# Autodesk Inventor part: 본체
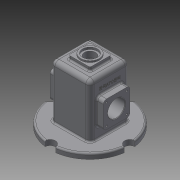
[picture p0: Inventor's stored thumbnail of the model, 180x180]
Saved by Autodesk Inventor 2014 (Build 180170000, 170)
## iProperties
Created: 2018-07
Part Number: 본체
Material: 알루미늄 6061
Document SubType Name: Modeling
Designer: kh
Density: 2.71 g/cm^3
Appearance: 기본값
Mass: 912.8 g
Surface Area: 1017.53 cm^2
Volume: 336.827 cm^3
Author: kh
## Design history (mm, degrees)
sketch "스케치1"
  geometry: L1 (37, 55)-(-37, 55); L2 (-37, 55)-(-37, -55); L3 (-37, -55)-(37, -55); L4 (37, -55)-(37, 55); 2 further points
  constraints: 8 end point, 2 parallel, 1 horizontal, 1 midpoint, 1 perpendicular, 1 vertical alignment
  dimensions: "d0" = 74 distance of L2.end L3.end; "d1" = 110 distance of L1.end L2.end; "d2" = 55 distance from line of point (0, 0) L3
extrude "돌출1" new body sketch "스케치1" stored distance "d3" = 74; taper "d4" = 0 deg
fillet "모깎기1" dims "d5" = 8
fillet "모깎기2" dims "d6" = 8
sketch "스케치5"
  geometry: L1 (9, 49)-(49, 49); L2 (49, 49)-(49, 9); L3 (49, 9)-(9, 9); L4 (9, 9)-(9, 49); L5 (9, 49)-(49, 9); L6 (49, 49)-(9, 9); 1 further point
  constraints: 12 end point, 2 midpoint, 2 parallel, 1 horizontal, 1 perpendicular
  dimensions: "d18" = 40 distance of L2.end L3.end; "d19" = 40 distance of L1.end L2.end (= d18)
extrude "돌출4" join sketch "스케치5" distance "d20" = 10; taper "d21" = 0 deg
sketch "스케치6"
  geometry: L1 (49, 49)-(9, 49) reference; L2 (9, 49)-(9, 9) reference; L3 (9, 9)-(49, 9) reference; L4 (49, 9)-(49, 49) reference; C1 r 17.5 at (29, 29); 1 further point
  constraints: 1 centre point, 1 coincident
  dimensions: "d22" = 35 diameter of C1
extrude "돌출5" cut sketch "스케치6" distance "d23" = 3; taper "d24" = 0 deg
node "작업 평면2"
sketch "스케치7"
  geometry: C1 r 14 at (0, 0); C2 r 10.5 at (0, 0); 1 further point
  constraints: 2 centre point, 2 coincident
  dimensions: "d26" = 28 diameter of C1; "d27" = 21 diameter of C2
extrude "돌출6" cut sketch "스케치7" stored distance "d28" = 3; taper "d29" = 0 deg
extrude "돌출7" cut sketch "스케치7" stored distance "d30" = 3; taper "d31" = 0 deg
sketch "스케치8"
  geometry: L1 (0, 0)-(58, 0) reference; L2 (-8, -66)-(-8, -8) reference; L3 (58, -74)-(0, -74) reference; L4 (66, -66)-(66, -8) reference; C1 r 75 at (29, -37); A1 r 8 centre (58, -8) between (66, -8) and (58, 0) reference; A2 r 8 centre (0, -8) between (0, 0) and (-8, -8) reference; A3 r 8 centre (0, -66) between (-8, -66) and (0, -74) reference; A4 r 8 centre (58, -66) between (58, -74) and (66, -66) reference; 1 further point
  constraints: 1 centre point, 1 coincident
  dimensions: "d32" = 150 diameter of C1
extrude "돌출8" join sketch "스케치8" distance "d33" = 10; taper "d34" = 0 deg
fillet "모깎기3" dims "d35" = 3
fillet "모깎기4" dims "d36" = 3
sketch "스케치9"
  geometry: L1 (0, 0)-(-75, 0); C1 r 10 at (-75, 0); 1 further point
  constraints: 2 end point, 1 centre point, 1 coincident, 1 horizontal alignment, 1 other
  dimensions: "d37" = 10 radius of C1
extrude "돌출9" cut sketch "스케치9" stored distance "d38" = 10; taper "d39" = 0 deg
sketch "스케치10"
  geometry: L1 (22, 4)-(72, 4); L2 (72, 4)-(72, 54); L3 (72, 54)-(22, 54); L4 (22, 54)-(22, 4); L5 (22, 4)-(72, 54); L6 (72, 4)-(22, 54); 1 further point
  constraints: 12 end point, 2 midpoint, 2 parallel, 1 horizontal, 1 perpendicular
  dimensions: "d43" = 50 distance of L3.end L2.end; "d44" = 50 distance of L1.end L2.end (= d43)
extrude "돌출10" join sketch "스케치10" distance "d45" = 13; taper "d46" = 0 deg
fillet "모깎기5" dims "d47" = 6
fillet "모깎기6" dims "d48" = 3
node "작업 평면3"
sketch "스케치11"
  geometry: L1 (-3, 61)-(61, 61); L2 (61, 61)-(61, -3); L3 (61, -3)-(-3, -3); L4 (-3, -3)-(-3, 61); L5 (-3, 61)-(61, -3); L6 (61, 61)-(-3, -3); 1 further point
  constraints: 12 end point, 2 midpoint, 2 parallel, 1 horizontal, 1 perpendicular
  dimensions: "d50" = 64 distance of L2.end L3.end; "d51" = 64 distance of L1.end L2.end (= d50)
extrude "돌출11" cut sketch "스케치11" stored distance "d52" = 13; taper "d53" = 0 deg
fillet "모깎기7" dims "d54" = 3
fillet "모깎기8" dims "d55" = 3
node "작업 평면4"
sketch "스케치12"
  geometry: C1 r 25 at (-55, 29); 1 further point
  constraints: 1 centre point, 1 coincident
  dimensions: "d57" = 50 diameter of C1
extrude "돌출12" join sketch "스케치12" stored distance "d58" = 13; taper "d59" = -20 deg
sketch "스케치13"
  geometry: C1 r 16 at (47, 29); 1 further point
  constraints: 1 centre point, 1 coincident
  dimensions: "d60" = 32 diameter of C1
extrude "돌출13" cut sketch "스케치13" stored distance "d61" = 13; taper "d62" = 0 deg
chamfer "모따기1" distance "d63" = 1; stored, may be unused: second distance "d64" = 2, angle "d65" = 45 deg
sketch "스케치14"
  geometry: L1 (66, 54)-(28, 54) reference; L2 (22, 48)-(22, 10) reference; L3 (28, 4)-(66, 4) reference; L4 (72, 10)-(72, 48) reference; C1 r 17 at (47, 29) reference; A1 r 6 centre (66, 48) between (72, 48) and (66, 54) reference; A2 r 6 centre (28, 48) between (28, 54) and (22, 48) reference; A3 r 6 centre (28, 10) between (22, 10) and (28, 4) reference; A4 r 6 centre (66, 10) between (66, 4) and (72, 10) reference; 2 further points
  constraints: 1 coincident
hole "구멍1" sketch "스케치14" at (28, 10) diameter "d66" = 3.242; stored, may be unused: countersink angle "d70" = 90 deg, drill point angle "d72" = 118 deg; dims "d67" = 8, "d68" = 4, "d69" = 2, "d71" = 10
fillet "모깎기9" dims "d77" = 3
fillet "모깎기10" dims "d78" = 3
sketch "스케치15"
  geometry: L1 (-18, 46.5)-(-18, 11.5) reference; L2 (89, 66)-(0, 66) reference; 2 further points
  constraints: 1 other
  dimensions: "d79" = 30 distance from line of L1 point (12, 29); "d80" = 37 distance from line of L2 point (12, 29)
feature "엠보싱1" sketch "스케치15" dims "d18" = 40, "d19" = 40 (= d18), "d81" = 0.5, "d82" = 0
node "솔리드1"
pattern_circular "원형 패턴1" dims angle "d41" = 360 deg
mirror "대칭1"
mirror "대칭2"
pattern_linear "직사각형 패턴1"
mirror "대칭3"
node "투영된 루프2"
node "투영된 루프3"
node "투영된 루프4"
node "투영된 루프5"
other parameters: "d25" = -4, "d49" = -5, "d56" = 7
